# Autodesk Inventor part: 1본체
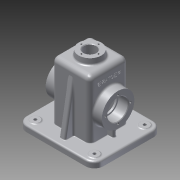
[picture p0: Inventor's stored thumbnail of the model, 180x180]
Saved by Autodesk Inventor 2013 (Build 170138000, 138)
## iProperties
Created: 2016-01
Part Number: 1본체
Material: 알루미늄 6061
Document SubType Name: Modeling
Designer: Administrator
Density: 2.71 g/cm^3
Mass: 874.944 g
Surface Area: 893.712 cm^2
Volume: 322.858 cm^3
Author: Administrator
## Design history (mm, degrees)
sketch "스케치1"
  geometry: L1 (-65, 57.5)-(65, 57.5); L2 (65, 57.5)-(65, -57.5); L3 (65, -57.5)-(-65, -57.5); L4 (-65, -57.5)-(-65, 57.5); L5 (-65, 57.5)-(65, -57.5); L6 (65, 57.5)-(-65, -57.5); 1 further point
  constraints: 12 end point, 2 midpoint, 2 parallel, 1 horizontal, 1 perpendicular
  dimensions: "d0" = 130 distance of L1.start L1.end; "d2" = 115 distance of L1.end L2.end
extrude "돌출1" new body sketch "스케치1" distance "d3" = 10; taper "d4" = 0 deg
fillet "모깎기1" dims "d5" = 15
sketch "스케치3"
  geometry: L1 (32.5, -32.5)-(-32.5, -32.5); L2 (-32.5, -32.5)-(-32.5, 32.5); L3 (-32.5, 32.5)-(32.5, 32.5); L4 (32.5, 32.5)-(32.5, -32.5); L5 (32.5, -32.5)-(-32.5, 32.5); L6 (-32.5, -32.5)-(32.5, 32.5); L7 (50, 57.5)-(-50, 57.5) reference; 1 further point
  constraints: 12 end point, 2 midpoint, 2 parallel, 1 horizontal, 1 perpendicular
  dimensions: "d134" = 65 distance of L2.end L3.end; "d136" = 25 distance between parallel lines of L3 L7
extrude "돌출2" join sketch "스케치3" distance "d16" = 98; taper "d17" = 0 deg
sketch "스케치4"
  geometry: C1 r 20 at (0, 0); 1 further point
  constraints: 1 centre point, 1 coincident
  dimensions: "d18" = 40 diameter of C1
extrude "돌출3" join sketch "스케치4" distance "d19" = 10; taper "d20" = 0 deg
sketch "스케치7"
  geometry: C1 r 7.5 at (-50, 42.5); A1 r 15 centre (-50, 42.5) between (-50, 57.5) and (-65, 42.5) reference; 1 further point
  constraints: 1 centre point, 1 coincident
  dimensions: "d33" = 15 diameter of C1
extrude "돌출6" join sketch "스케치7" distance "d34" = 1; taper "d35" = 0 deg
sketch "스케치9"
  geometry: L1 (-50, 52.5)-(50, 52.5); L2 (60, 42.5)-(60, -42.5); L3 (50, -52.5)-(-50, -52.5); L4 (-60, -42.5)-(-60, 42.5); L5 (-60, 52.5)-(60, -52.5); L6 (60, 52.5)-(-60, -52.5); A1 r 10 centre (-50, 42.5) between (-50, 52.5) and (-60, 42.5); A2 r 10 centre (50, 42.5) between (60, 42.5) and (50, 52.5); A3 r 10 centre (50, -42.5) between (50, -52.5) and (60, -42.5); A4 r 10 centre (-50, -42.5) between (-60, -42.5) and (-50, -52.5); 1 further point
  constraints: 12 end point, 8 point on circle, 8 point on line, 8 tangent, 4 centre point, 3 equal radius, 2 midpoint, 2 parallel, 1 horizontal, 1 perpendicular
  dimensions: "d38" = 120 distance of L5.start L6.start; "d39" = 105 distance of L6.start L5.end; "d40" = 10 radius of A1
extrude "돌출7" join sketch "스케치9" distance "d41" = 2; taper "d42" = 0 deg
sketch "스케치10"
  geometry: 2 further points
  dimensions: "d43" = 42.5 vertical distance of point (0, 0) point (50, 42.5); "d44" = 50 horizontal distance of point (50, 42.5) point (0, 0)
hole "구멍2" sketch "스케치10" at (50, 42.5) diameter "d45" = 5; stored, may be unused: countersink angle "d49" = 90 deg, drill point angle "d51" = 118 deg; dims "d46" = 6, "d47" = 4, "d48" = 2, "d50" = 8
sketch "스케치17"
  geometry: L1 (0, 65)-(0, 0) reference; L2 (10, 75)-(10, -10) reference; L3 (0, 0)-(-98, 0) reference; L4 (-98, 0)-(-98, 65) reference; L5 (-98, 65)-(0, 65) reference; L6 (0, 0)-(0, 65) reference; L7 (0, -25)-(0, 0) reference; L8 (10, -25)-(0, -25) reference; L9 (10, -20)-(10, -25) reference; L10 (12, -20)-(10, -20) reference; L11 (12, 85)-(12, -20) reference; L12 (10, 85)-(12, 85) reference; L13 (10, 90)-(10, 85) reference; L14 (0, 90)-(10, 90) reference; L15 (0, 65)-(0, 90) reference; L16 (0, 0)-(-98, 0) reference; L17 (-98, 0)-(-98, 65) reference; L18 (-98, 65)-(0, 65) reference; L19 (0, 0)-(0, 65) reference; L20 (0, -25)-(0, 0) reference; L21 (10, -25)-(0, -25) reference; L22 (10, -20)-(10, -25) reference; L23 (12, -20)-(10, -20) reference; L24 (12, 85)-(12, -20) reference; L25 (10, 85)-(12, 85) reference; L26 (10, 90)-(10, 85) reference; L27 (0, 90)-(10, 90) reference; L28 (0, 65)-(0, 90) reference; L29 (0, 0)-(-98, 0) reference; L30 (-98, 0)-(-98, 65) reference; L31 (-98, 65)-(0, 65) reference; L32 (0, 0)-(0, 65) reference; L33 (0, -25)-(0, 0) reference; L34 (10, -25)-(0, -25) reference; L35 (10, -20)-(10, -25) reference; L36 (12, -20)-(10, -20) reference; L37 (12, 85)-(12, -20) reference; L38 (10, 85)-(12, 85) reference; L39 (10, 90)-(10, 85) reference; L40 (0, 90)-(10, 90) reference; L41 (0, 65)-(0, 90) reference; L42 (0, 0)-(-98, 0) reference; L43 (-98, 0)-(-98, 65) reference; L44 (-98, 65)-(0, 65) reference; L45 (0, 0)-(0, 65) reference; L46 (0, -25)-(0, 0) reference; L47 (10, -25)-(0, -25) reference; L48 (10, -20)-(10, -25) reference; L49 (12, -20)-(10, -20) reference; L50 (12, 85)-(12, -20) reference; L51 (10, 85)-(12, 85) reference; L52 (10, 90)-(10, 85) reference; L53 (0, 90)-(10, 90) reference; L54 (0, 65)-(0, 90) reference; L55 (0, -10)-(0, 75) reference; C1 r 27.5 at (-43, 32.5); 2 further points
  constraints: 1 centre point, 1 horizontal alignment, 1 midpoint
  dimensions: "d127" = 55 diameter of C1; "d129" = 55 distance from line of L11 C1.centre
extrude "돌출11" join sketch "스케치17" distance "d130" = 15; taper "d132" = 0 deg; dims "d131" = 80, "d133" = 0
sketch "스케치18"
  geometry: L1 (-32.5, 10)-(-32.5, 108) reference; L2 (-32.5, 108)-(-20, 108) reference; L3 (-20, 108)-(-20, 118) reference; L4 (-20, 118)-(20, 118) reference; L5 (20, 118)-(20, 108) reference; L6 (20, 108)-(32.5, 108) reference; L7 (32.5, 108)-(32.5, 10) reference; L8 (32.5, 10)-(57.5, 10) reference; L9 (57.5, 10)-(57.5, 0) reference; L10 (57.5, 0)-(52.5, 0) reference; L11 (52.5, 0)-(52.5, -2) reference; L12 (52.5, -2)-(-52.5, -2) reference; L13 (-52.5, -2)-(-52.5, 0) reference; L14 (-52.5, 0)-(-57.5, 0) reference; L15 (-57.5, 0)-(-57.5, 10) reference; L16 (-57.5, 10)-(-32.5, 10) reference; L17 (-27.5, -2)-(27.5, -2); L18 (27.5, -2)-(27.5, 103); L19 (27.5, 103)-(-27.5, 103); L20 (-27.5, 103)-(-27.5, -2); 2 further points
  constraints: 8 end point, 2 parallel, 1 horizontal, 1 midpoint, 1 perpendicular, 1 point on line, 1 vertical alignment
  dimensions: "d137" = 105 distance of L17.end L18.end; "d140" = 5 distance between parallel lines of L7 L18
extrude "돌출12" cut sketch "스케치18" stored distance "d141" = 55; taper "d142" = 0 deg
fillet "모깎기8" dims "d143" = 8
fillet "모깎기9" dims "d144" = 8
feature "면 기울기3" dims angle "d145" = 5 deg
hole "구멍7" diameter "d148" = 30; stored, may be unused: countersink angle "d152" = 90 deg, drill point angle "d154" = 118 deg; dims "d146" = 10, "d147" = 10, "d149" = 8, "d150" = 35, "d151" = 17, "d153" = 35
hole "구멍8" diameter "d157" = 35; stored, may be unused: countersink angle "d161" = 90 deg, drill point angle "d163" = 0 deg; dims "d155" = 10, "d156" = 10, "d158" = 8, "d159" = 35, "d160" = 17, "d162" = 17
hole "구멍9" diameter "d166" = 21; stored, may be unused: countersink angle "d170" = 90 deg, drill point angle "d172" = 0 deg; dims "d164" = 10, "d165" = 10, "d167" = 8, "d168" = 35, "d169" = 17, "d171" = 17
sketch "스케치19"
  geometry: C1 r 17.5 at (0, 0) reference; 2 further points
  constraints: 1 horizontal alignment
  dimensions: "d173" = 21 distance of point (-21, 0) C1.centre
hole "구멍10" sketch "스케치19" at (-21, 0) diameter "d174" = 3.242; stored, may be unused: countersink angle "d178" = 90 deg, drill point angle "d180" = 118 deg; dims "d175" = 8, "d176" = 35, "d177" = 17, "d179" = 10
sketch "스케치20"
  geometry: C1 r 10.5 at (0, 0) reference; 1 further point
  constraints: 1 horizontal alignment
  dimensions: "d184" = 14.5 distance of C1.centre point (14.5, 0)
hole "구멍11" sketch "스케치20" at (14.5, 0) diameter "d185" = 2.459; stored, may be unused: countersink angle "d189" = 90 deg, drill point angle "d191" = 118 deg; dims "d186" = 7, "d187" = 35, "d188" = 17, "d190" = 9
sketch "스케치21"
  geometry: L1 (24.5, -32.5)-(-24.5, -32.5) reference; L2 (-50, -57.5)-(50, -57.5) reference; L3 (-5, -32.5)-(5, -32.5); L4 (5, -32.5)-(5, -47.5); L5 (5, -47.5)-(-5, -47.5); L6 (-5, -47.5)-(-5, -32.5); 2 further points
  constraints: 8 end point, 2 parallel, 1 horizontal, 1 midpoint, 1 perpendicular, 1 point on line, 1 vertical alignment
  dimensions: "d195" = 10 distance of L4.end L5.end; "d198" = 10 distance between parallel lines of L5 L2
extrude "돌출13" join sketch "스케치21" distance "d199" = 105; taper "d200" = 0 deg
feature "면 기울기4" dims angle "d201" = 10 deg
feature "면 기울기5" dims angle "d202" = 10 deg
sketch "스케치22"
  geometry: L1 (32.5, 24.5)-(32.5, -24.5) reference; L2 (32.5, 3)-(42.5, 3); L3 (42.5, 3)-(42.5, -3); L4 (42.5, -3)-(32.5, -3); L5 (32.5, -3)-(32.5, 3); 2 further points
  constraints: 8 end point, 2 parallel, 1 horizontal, 1 horizontal alignment, 1 midpoint, 1 perpendicular, 1 point on line
  dimensions: "d203" = 10 distance of L3.end L4.end; "d206" = 6 distance of L2.end L3.end
extrude "돌출14" join sketch "스케치22" stored distance "d207" = 0; taper "d208" = 0 deg
fillet "모깎기10" dims "d209" = 3
fillet "모깎기11" dims "d210" = 3
fillet "모깎기12" dims "d211" = 1
fillet "모깎기13" dims "d212" = 3
fillet "모깎기14" dims "d213" = 3
fillet "모깎기17" dims "d216" = 3
fillet "모깎기18" dims "d217" = 0.3
chamfer "모따기1" distance "d218" = 1; stored, may be unused: second distance "d219" = 2, angle "d220" = 45 deg
node "작업 평면3"
sketch "스케치23"
  geometry: L1 (43.625, 18)-(5.375, 18) reference; 3 further points
  constraints: 1 midpoint, 1 vertical alignment, 1 other
  dimensions: "d221" = 27 distance from line of L1 point (24.5, -9)
feature "엠보싱2" sketch "스케치23" dims "d134" = 65, "d136" = 25, "d222" = 0.5, "d223" = 0
fillet "모깎기19" dims "d224" = 3
fillet "모깎기20" dims "d225" = 3
sketch "스케치11"
  geometry: L1 (27.5, -2)-(-27.5, -2); L2 (-27.5, -2)-(-27.5, 103); L3 (-27.5, 103)-(27.5, 103); L4 (27.5, 103)-(27.5, -2); L5 (65, 10)-(65, 0) reference; L6 (65, 0)-(60, 0) reference; L7 (60, 0)-(60, -2) reference; L8 (60, -2)-(-60, -2) reference; L9 (-60, -2)-(-60, 0) reference; L10 (-60, 0)-(-65, 0) reference; L11 (-65, 0)-(-65, 10) reference; L12 (-65, 10)-(-40, 10) reference; L13 (-40, 10)-(-40, 108) reference; L14 (-40, 108)-(-20, 108) reference; L15 (-20, 108)-(-20, 118) reference; L16 (-20, 118)-(20, 118) reference; L17 (20, 118)-(20, 108) reference; L18 (20, 108)-(40, 108) reference; L19 (40, 108)-(40, 10) reference; L20 (40, 10)-(65, 10) reference; 3 further points
  constraints: 8 end point, 2 coincident, 2 midpoint, 2 parallel, 1 horizontal, 1 perpendicular
  dimensions: "d52" = 55 distance of L2.end L3.end; "d54" = 105 distance of L3.end L1.start
extrude "돌출8" cut sketch "스케치11" stored distance "d55" = 55; taper "d56" = 0 deg
sketch "스케치13"
  geometry: L1 (32.5, -32.5)-(-32.5, -32.5) reference; L2 (-3, -32.5)-(3, -32.5); L3 (3, -32.5)-(3, -42.5); L4 (3, -42.5)-(-3, -42.5); L5 (-3, -42.5)-(-3, -32.5); 2 further points
  constraints: 8 end point, 2 parallel, 1 horizontal, 1 midpoint, 1 perpendicular, 1 point on line, 1 vertical alignment
  dimensions: "d59" = 10 distance of L2.end L3.end; "d61" = 6 distance of L3.end L4.end
extrude "돌출9" join sketch "스케치13" stored distance "d62" = 10; taper "d63" = 0 deg
hole "구멍3" diameter "d66" = 30; stored, may be unused: countersink angle "d70" = 90 deg, drill point angle "d72" = 118 deg; dims "d64" = 10, "d65" = 10, "d67" = 6, "d68" = 35, "d69" = 17, "d71" = 8
hole "구멍4" diameter "d75" = 35; stored, may be unused: countersink angle "d79" = 90 deg, drill point angle "d81" = 0 deg; dims "d76" = 6, "d77" = 35, "d78" = 17, "d80" = 17, "d93" = 10, "d94" = 10
hole "구멍5" diameter "d84" = 21; stored, may be unused: countersink angle "d88" = 90 deg, drill point angle "d90" = 0 deg; dims "d85" = 6, "d86" = 35, "d87" = 17, "d89" = 21, "d91" = 10, "d92" = 10
sketch "스케치14"
  geometry: C1 r 17.5 at (0, 0) reference; 2 further points
  constraints: 1 vertical alignment
  dimensions: "d95" = 21 distance of point (0, 21) C1.centre
hole "구멍6" sketch "스케치14" at (0, 21) diameter "d96" = 3.242; stored, may be unused: countersink angle "d100" = 90 deg, drill point angle "d102" = 118 deg; dims "d97" = 8, "d98" = 35, "d99" = 17, "d101" = 10
fillet "모깎기2" dims "d106" = 8
fillet "모깎기3" dims "d107" = 8
node "작업 평면2"
sketch "스케치15"
  geometry: L1 (-28, -102)-(-28, -100) reference; L2 (-28, -100)-(-33, -100) reference; L3 (-33, -100)-(-33, -90) reference; L4 (-33, -90)-(0, -90) reference; L5 (0, -90)-(0, 0) reference; L6 (64, -90)-(64, 0) reference; L7 (64, -90)-(97, -90) reference; L8 (97, -90)-(97, -100) reference; L9 (97, -100)-(92, -100) reference; L10 (92, -100)-(92, -102) reference; L11 (92, -102)-(-28, -102) reference; L12 (0, -90)-(64, -90) reference; L13 (0, 0)-(64, 0) reference; L14 (52, 18)-(12, 18) reference; L15 (-8, 0)-(-8, -90) reference; C1 r 17.5 at (32, -45) reference; C2 r 27.5 at (32, -45) reference; 2 further points
  constraints: 1 vertical alignment, 1 other
  dimensions: "d108" = 27 distance from line of point (32, -9) L14
feature "엠보싱1" sketch "스케치15" dims "d109" = 0.5, "d110" = 0, "d134" = 65, "d136" = 25
fillet "모깎기4" dims "d111" = 3
feature "면 기울기1" dims angle "d112" = 5 deg
fillet "모깎기5" dims "d113" = 3
fillet "모깎기6" dims "d114" = 3
sketch "스케치16"
  geometry: L1 (40, 24.5)-(40, -24.5) reference; L2 (40, 5)-(55, 5); L3 (55, 5)-(55, -5); L4 (55, -5)-(40, -5); L5 (40, -5)-(40, 5); L6 (65, -42.5)-(65, 42.5) reference; 3 further points
  constraints: 8 end point, 2 horizontal alignment, 2 midpoint, 2 parallel, 1 horizontal, 1 perpendicular, 1 point on line
  dimensions: "d119" = 10 distance of L2.end L3.end; "d121" = 10 distance between parallel lines of L3 L6
extrude "돌출10" join sketch "스케치16" distance "d122" = 105; taper "d123" = 0 deg
feature "면 기울기2" dims angle "d124" = 10 deg
fillet "모깎기7" dims "d125" = 3
node "솔리드1"
mirror "대칭1"
mirror "대칭2"
pattern_circular "원형 패턴2" dims angle "d182" = 360 deg
mirror "대칭5"
pattern_circular "원형 패턴3" dims angle "d193" = 360 deg
mirror "대칭6"
mirror "대칭7"
pattern_circular "원형 패턴1" dims angle "d104" = 360 deg
mirror "대칭3"
mirror "대칭4"
node "절단 모서리 투영2"
node "절단 모서리 투영4"
node "절단 모서리 투영5"
node "절단 모서리 투영6"
node "절단 모서리 투영7"
node "절단 모서리 투영8"
node "절단 모서리 투영9"
